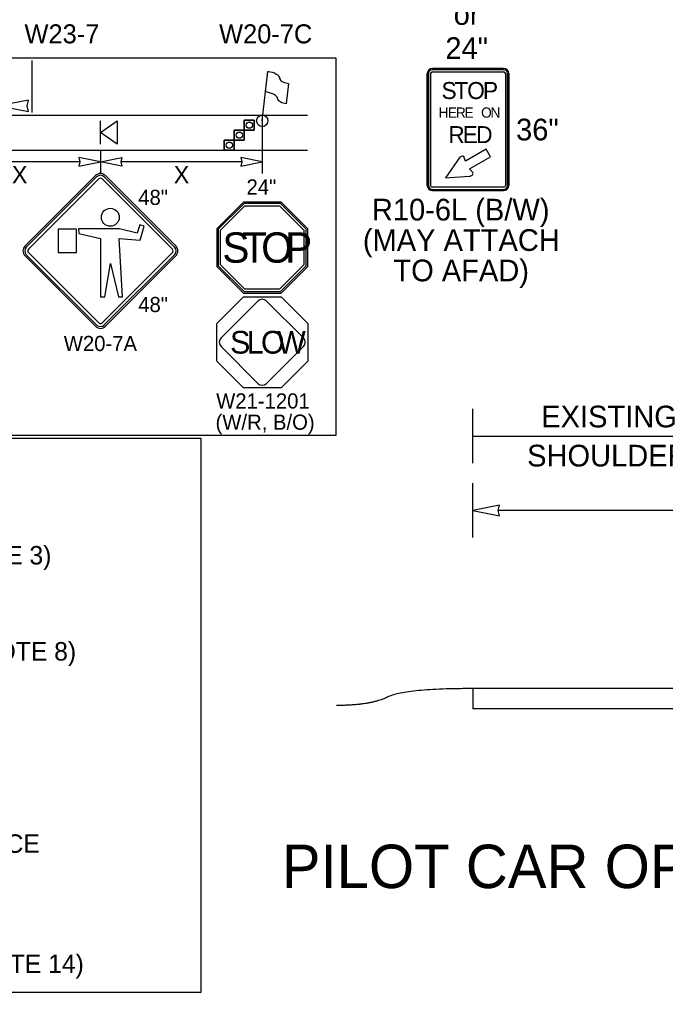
# Model space of a CAD drawing. Extents: x 99999.1 to 100095.7, y 99995 to 100010.7.
# Drawn here: x 100042.622 to 100045, y 100001.176 to 100004.76 of the extents above; entities that cross this region are included whole.
import ezdxf

# ---------------------------------------------------------------- set-up
doc = ezdxf.new("R2010")
doc.units = 0
for name, color, linetype in [('RD_ED_ShoulderPavedEdge', 7, 'Continuous'), ('RD_MK_LineEdgeWhite', 7, 'Continuous'), ('SH_DE_DetailHeading1Text', 7, 'Continuous'), ('TR_SN_ConstructionSigns', 7, 'Continuous'), ('TR_WZ_FlaggingStation', 7, 'Continuous'), ('TR_WZ_PortableSignMountBlk-Org', 7, 'Continuous'), ('TR_WZ_TrafficCone', 7, 'Continuous'), ('TR_WZ_WorkZoneDetails', 7, 'Continuous'), ('TR_WZ_WorkZoneTextCurrent', 7, 'Continuous')]:
    doc.layers.add(name, color=color, linetype=linetype)

msp = doc.modelspace()

# ---------------------------------------------------------------- linework, layer by layer
at = {"layer": 'RD_ED_ShoulderPavedEdge'}
msp.add_line((100040.2, 100004.2788), (100043.6825, 100004.2788), dxfattribs=at)
at = {"layer": 'RD_MK_LineEdgeWhite'}
msp.add_line((100040.2, 100004.4079), (100043.6825, 100004.4079), dxfattribs=at)
at = {"layer": 'TR_SN_ConstructionSigns'}
for p, q in [((100044.4041, 100004.5796), (100044.1416, 100004.5796)), ((100044.1416, 100004.5796), (100044.4041, 100004.5796)), ((100044.4041, 100004.5796), (100044.1416, 100004.5796)), ((100044.4041, 100004.5749), (100044.1416, 100004.5749)), ((100044.1229, 100004.5609), (100044.1229, 100004.1484)), ((100044.1229, 100004.1484), (100044.1229, 100004.5609)), ((100044.1229, 100004.5609), (100044.1229, 100004.1484)), ((100044.1276, 100004.5609), (100044.1276, 100004.1484)), ((100044.1354, 100004.1484), (100044.1354, 100004.5609)), ((100044.1416, 100004.5671), (100044.4041, 100004.5671)), ((100044.4104, 100004.5609), (100044.4104, 100004.1484)), ((100044.4182, 100004.1484), (100044.4182, 100004.5609)), ((100044.4229, 100004.1484), (100044.4229, 100004.5609)), ((100044.4229, 100004.5609), (100044.4229, 100004.1484)), ((100044.4229, 100004.1484), (100044.4229, 100004.5609)), ((100044.2424, 100004.2523), (100044.1898, 100004.1766)), ((100044.3396, 100004.2827), (100044.263, 100004.2385)), ((100044.2786, 100004.2096), (100044.356, 100004.2543)), ((100044.356, 100004.2543), (100044.3396, 100004.2827)), ((100044.263, 100004.2385), (100044.2592, 100004.2511)), ((100042.901, 100004.185), (100042.642, 100003.926)), ((100042.9056, 100004.1804), (100042.6466, 100003.9214)), ((100043.1923, 100003.9214), (100042.9333, 100004.1804)), ((100043.1969, 100003.926), (100042.938, 100004.185)), ((100044.1898, 100004.1766), (100044.2776, 100004.1827)), ((100044.2909, 100004.1959), (100044.2786, 100004.2096)), ((100042.6543, 100003.9137), (100042.9133, 100004.1726)), ((100042.9256, 100004.1726), (100043.1846, 100003.9137)), ((100044.4041, 100004.1421), (100044.1416, 100004.1421)), ((100044.1416, 100004.1343), (100044.4041, 100004.1343)), ((100044.1416, 100004.1296), (100044.4041, 100004.1296)), ((100044.4041, 100004.1296), (100044.1416, 100004.1296)), ((100044.1416, 100004.1296), (100044.4041, 100004.1296)), ((100043.446, 100004.0874), (100043.3479, 100003.9893)), ((100043.4482, 100004.0822), (100043.3531, 100003.9872)), ((100043.3619, 100003.9835), (100043.4518, 100004.0734)), ((100043.5847, 100004.0874), (100043.446, 100004.0874)), ((100043.5825, 100004.0822), (100043.4482, 100004.0822)), ((100043.4518, 100004.0734), (100043.5789, 100004.0734)), ((100043.5789, 100004.0734), (100043.6688, 100003.9835)), ((100043.6775, 100003.9872), (100043.5825, 100004.0822)), ((100043.6828, 100003.9893), (100043.5847, 100004.0874)), ((100043.3479, 100003.9893), (100043.3479, 100003.8506)), ((100043.3531, 100003.9872), (100043.3531, 100003.8528)), ((100043.3619, 100003.8564), (100043.3619, 100003.9835)), ((100043.6688, 100003.9835), (100043.6688, 100003.8564)), ((100043.6775, 100003.8528), (100043.6775, 100003.9872)), ((100043.6828, 100003.8506), (100043.6828, 100003.9893)), ((100042.6466, 100003.8936), (100042.9056, 100003.6347)), ((100042.9133, 100003.6424), (100042.6543, 100003.9013)), ((100043.1846, 100003.9013), (100042.9256, 100003.6424)), ((100042.9333, 100003.6347), (100043.1923, 100003.8936)), ((100042.642, 100003.889), (100042.901, 100003.63)), ((100042.938, 100003.63), (100043.1969, 100003.889)), ((100043.3479, 100003.8506), (100043.446, 100003.7525)), ((100043.3531, 100003.8528), (100043.4482, 100003.7578)), ((100043.4518, 100003.7665), (100043.3619, 100003.8564)), ((100043.6688, 100003.8564), (100043.5789, 100003.7665)), ((100043.5825, 100003.7578), (100043.6775, 100003.8528)), ((100043.5847, 100003.7525), (100043.6828, 100003.8506)), ((100043.446, 100003.7525), (100043.5847, 100003.7525)), ((100043.4482, 100003.7578), (100043.5825, 100003.7578)), ((100043.5789, 100003.7665), (100043.4518, 100003.7665)), ((100043.4996, 100003.7228), (100043.3637, 100003.587)), ((100043.667, 100003.587), (100043.5311, 100003.7228)), ((100043.3637, 100003.5554), (100043.4996, 100003.4195)), ((100043.5311, 100003.4195), (100043.667, 100003.5554))]:
    msp.add_line(p, q, dxfattribs=at)
for points in [[(100042.8394, 100003.9884), (100042.8404, 100003.9716), (100042.9199, 100003.9531), (100042.9199, 100003.7389), (100042.9354, 100003.7389), (100042.9572, 100003.8606), (100042.9863, 100003.7389), (100043.001, 100003.7389), (100042.9881, 100003.953), (100043.0658, 100003.9467), (100043.0805, 100003.9987), (100043.0645, 100004.0032), (100043.0542, 100003.9735), (100042.99, 100003.9884)], [(100042.7635, 100003.9882), (100042.7635, 100003.9012), (100042.8314, 100003.9012), (100042.8314, 100003.9882)], [(100043.6828, 100003.6405), (100043.6828, 100003.5018), (100043.5847, 100003.4037), (100043.446, 100003.4037), (100043.3479, 100003.5018), (100043.3479, 100003.6405), (100043.446, 100003.7386), (100043.5847, 100003.7386)]]:
    msp.add_lwpolyline(points, close=True, dxfattribs=at)
msp.add_circle((100042.9559, 100004.0315), 0.0329, dxfattribs=at)
for centre, radius, start, end in [((100044.1416, 100004.5609), 0.0187, 90, 180), ((100044.1416, 100004.5609), 0.0187, 90, 180), ((100044.1416, 100004.5609), 0.0187, 90, 180), ((100044.1416, 100004.5609), 0.0141, 90, 180), ((100044.4041, 100004.5609), 0.0187, 0, 90), ((100044.4041, 100004.5609), 0.0187, 0, 90), ((100044.4041, 100004.5609), 0.0187, 0, 90), ((100044.4041, 100004.5609), 0.0141, 0, 90), ((100044.1416, 100004.5609), 0.00625, 90, 180), ((100044.4041, 100004.5609), 0.00625, 0, 90), ((100042.9195, 100004.1665), 0.0262, 45, 135), ((100042.9195, 100004.1665), 0.0196, 45, 135), ((100042.9195, 100004.1665), 0.00872, 45, 135), ((100044.1416, 100004.1484), 0.0187, 180, 270), ((100044.1416, 100004.1484), 0.0187, 180, 270), ((100044.1416, 100004.1484), 0.0187, 180, 270), ((100044.1416, 100004.1484), 0.0141, 180, 270), ((100044.1416, 100004.1484), 0.00625, 180, 270), ((100044.4041, 100004.1484), 0.0187, 270, 0), ((100044.4041, 100004.1484), 0.0187, 270, 0), ((100044.4041, 100004.1484), 0.0187, 270, 0), ((100044.4041, 100004.1484), 0.0141, 270, 0), ((100044.4041, 100004.1484), 0.00625, 270, 0), ((100042.6605, 100003.9075), 0.0262, 135, 225), ((100042.6605, 100003.9075), 0.0196, 135, 225), ((100042.6605, 100003.9075), 0.00872, 135, 225), ((100043.1784, 100003.9075), 0.00872, 315, 45), ((100043.1784, 100003.9075), 0.0196, 315, 45), ((100043.1784, 100003.9075), 0.0262, 315, 45), ((100043.5153, 100003.707), 0.0223, 45, 135), ((100042.9195, 100003.6485), 0.00872, 225, 315), ((100042.9195, 100003.6485), 0.0262, 225, 315), ((100042.9195, 100003.6485), 0.0196, 225, 315), ((100043.3795, 100003.5712), 0.0223, 135, 225), ((100043.6512, 100003.5712), 0.0223, 315, 45), ((100043.5153, 100003.4353), 0.0223, 225, 315)]:
    msp.add_arc(centre, radius, start, end, dxfattribs=at)
for centre, major_axis, start_param, end_param in [((100044.2492, 100004.248), (0.00934, 0.00539), 5.977036, 8.198856), ((100044.2816, 100004.1909), (-0.00913, -0.00527), 0.771965, 3.092601)]:
    msp.add_ellipse(centre, major_axis=major_axis, ratio=0.700347, start_param=start_param, end_param=end_param, dxfattribs=at)
at = {"layer": 'TR_WZ_FlaggingStation'}
for p, q in [((100043.5154, 100004.387), (100043.5361, 100004.5684)), ((100043.5277, 100004.4948), (100043.5361, 100004.5686)), ((100043.6123, 100004.5248), (100043.6037, 100004.4491)), ((100043.5277, 100004.4948), (100043.5277, 100004.4948))]:
    msp.add_line(p, q, dxfattribs=at)
for points in [[(100043.5361, 100004.5686), (100043.5398, 100004.5678), (100043.5514, 100004.5656), (100043.5603, 100004.5629), (100043.5665, 100004.559), (100043.5721, 100004.5559), (100043.5757, 100004.5515), (100043.5785, 100004.5464), (100043.5788, 100004.5424), (100043.5823, 100004.5365), (100043.5892, 100004.5317), (100043.5973, 100004.5283), (100043.6123, 100004.5248)], [(100043.6037, 100004.4491), (100043.5985, 100004.45), (100043.587, 100004.453), (100043.5769, 100004.4598), (100043.5727, 100004.4667), (100043.5702, 100004.4733), (100043.5643, 100004.4803), (100043.5572, 100004.4844), (100043.546, 100004.4889), (100043.5277, 100004.4948)]]:
    msp.add_lwpolyline(points, dxfattribs=at)
msp.add_circle((100043.5154, 100004.387), 0.021, dxfattribs=at)
at = {"layer": 'TR_WZ_PortableSignMountBlk-Org'}
msp.add_line((100042.9195, 100004.3003), (100042.9195, 100004.3864), dxfattribs=at)
msp.add_lwpolyline([(100042.9195, 100004.3433), (100042.9813, 100004.3864), (100042.9813, 100004.3003)], close=True, dxfattribs=at)
at = {"layer": 'TR_WZ_TrafficCone'}
for points in [[(100043.4491, 100004.389), (100043.4858, 100004.389), (100043.4858, 100004.3523), (100043.4491, 100004.3523), (100043.4491, 100004.389)], [(100043.4491, 100004.3523), (100043.4858, 100004.3523), (100043.4858, 100004.389), (100043.4491, 100004.389), (100043.4491, 100004.3523)], [(100043.4123, 100004.3523), (100043.4491, 100004.3523), (100043.4491, 100004.3155), (100043.4123, 100004.3155), (100043.4123, 100004.3523)], [(100043.4123, 100004.3155), (100043.4491, 100004.3155), (100043.4491, 100004.3523), (100043.4123, 100004.3523), (100043.4123, 100004.3155)], [(100043.3756, 100004.3155), (100043.4123, 100004.3155), (100043.4123, 100004.2788), (100043.3756, 100004.2788), (100043.3756, 100004.3155)], [(100043.3756, 100004.2788), (100043.4123, 100004.2788), (100043.4123, 100004.3155), (100043.3756, 100004.3155), (100043.3756, 100004.2788)]]:
    msp.add_lwpolyline(points, dxfattribs=at)
for centre in [(100043.4674, 100004.3706), (100043.4307, 100004.3339), (100043.3939, 100004.2971)]:
    msp.add_circle(centre, 0.0115, dxfattribs=at)
at = {"layer": 'TR_WZ_WorkZoneDetails'}
for p, q in [((100042.6686, 100004.4179), (100042.6686, 100004.6086)), ((100043.5154, 100004.4079), (100043.5154, 100004.1926)), ((100042.9195, 100004.2788), (100042.9195, 100004.1926)), ((100042.8438, 100004.2357), (100042.3992, 100004.2357)), ((100043.4397, 100004.2357), (100042.9952, 100004.2357)), ((100044.2907, 100003.1255), (100044.2907, 100003.3255)), ((100044.2907, 100003.2255), (100045.2907, 100003.2255)), ((100044.2907, 100002.8515), (100044.2907, 100003.0515)), ((100046.397, 100002.9515), (100044.3844, 100002.9515)), ((100044.2907, 100002.2954), (100044.2907, 100002.2204)), ((100048.6907, 100002.2954), (100044.2907, 100002.2954)), ((100048.6907, 100002.2204), (100044.2907, 100002.2204))]:
    msp.add_line(p, q, dxfattribs=at)
for points in [[(100042.5458, 100004.4419), (100042.655, 100004.4205), (100042.6499, 100004.4419), (100042.655, 100004.4633)], [(100042.9195, 100004.2357), (100042.8401, 100004.2513), (100042.8438, 100004.2357), (100042.8401, 100004.2201)], [(100042.9195, 100004.2357), (100042.9988, 100004.2513), (100042.9952, 100004.2357), (100042.9988, 100004.2201)], [(100043.5154, 100004.2357), (100043.4361, 100004.2513), (100043.4397, 100004.2357), (100043.4361, 100004.2201)], [(100044.2907, 100002.9515), (100044.389, 100002.9322), (100044.3844, 100002.9515), (100044.389, 100002.9708)]]:
    msp.add_lwpolyline(points, close=True, dxfattribs=at)
msp.add_open_spline([(100044.2907, 100002.2954), (100044.0395, 100002.2954), (100043.914, 100002.2333), (100043.7886, 100002.2333)], degree=2, dxfattribs=at)
at = {"layer": 'TR_WZ_WorkZoneTextCurrent'}
for points in [[(100040.1, 100004.6186), (100043.7858, 100004.6186), (100043.7858, 100003.2274), (100040.1, 100003.2274)], [(100040.1, 100003.2174), (100043.2886, 100003.2174), (100043.2886, 100001.1759), (100040.1, 100001.1759)]]:
    msp.add_lwpolyline(points, close=True, dxfattribs=at)

# ---------------------------------------------------------------- texts
at = {"layer": 'SH_DE_DetailHeading1Text'}
msp.add_text('PILOT CAR OPERATION FOR ALTERNATING 1-LANE, 2-WAY TRAFFIC: AFAD-CONTROLLED + TEMP. RUMBLE STRIPS', height=0.16, rotation=360, dxfattribs=at).set_placement((100043.5871, 100001.5606))
at = {"layer": 'TR_SN_ConstructionSigns'}
for s, height, p in [('or', 0.08, (100044.2201, 100004.7403)), ('W23-7', 0.07, (100042.64, 100004.6721)), ('W20-7C', 0.07, (100043.3563, 100004.6721)), ('24"', 0.08, (100044.1895, 100004.6146)), ('36"', 0.08, (100044.4498, 100004.3146)), ('48"', 0.05581, (100043.0588, 100004.0769)), ('R10-6L (B/W)', 0.08, (100043.919, 100004.0196)), ('(MAY ATTACH', 0.08, (100043.8858, 100003.9076)), ('TO AFAD)', 0.08, (100043.9982, 100003.7956)), ('48"', 0.05581, (100043.0588, 100003.6823)), ('W20-7A', 0.05581, (100042.7847, 100003.5387)), ('W21-1201', 0.05581, (100043.3457, 100003.327)), ('(W/R, B/O)', 0.05581, (100043.3434, 100003.2489))]:
    msp.add_text(s, height=height, rotation=360, dxfattribs=at).set_placement(p)
for s, height, p in [('S', 0.0625, (100044.1754, 100004.4671)), ('T', 0.0625, (100044.2229, 100004.4671)), ('O', 0.0625, (100044.2698, 100004.4671)), ('P', 0.0625, (100044.3279, 100004.4671)), ('H', 0.0375, (100044.1643, 100004.3984)), ('E', 0.0375, (100044.1988, 100004.3984)), ('R', 0.0375, (100044.2284, 100004.3984)), ('E', 0.0375, (100044.2603, 100004.3984)), ('O', 0.0375, (100044.3211, 100004.3984)), ('N', 0.0375, (100044.3559, 100004.3984)), ('R', 0.0625, (100044.2004, 100004.3046)), ('E', 0.0625, (100044.2535, 100004.3046)), ('D', 0.0625, (100044.3029, 100004.3046)), ('24"', 0.05581, (100043.4574, 100004.1153)), ('S', 0.1116, (100043.3686, 100003.8642)), ('T', 0.1116, (100043.4411, 100003.8642)), ('O', 0.1116, (100043.5114, 100003.8642)), ('P', 0.1116, (100043.5996, 100003.8642)), ('S', 0.0837, (100043.3969, 100003.5293)), ('L', 0.0837, (100043.458, 100003.5293)), ('O', 0.0837, (100043.5107, 100003.5293)), ('W', 0.0837, (100043.5702, 100003.5293))]:
    msp.add_text(s, height=height, dxfattribs=at).set_placement(p)
at = {"layer": 'TR_WZ_WorkZoneDetails'}
for s, p in [('EXISTING', (100044.5424, 100003.2575)), ('SHOULDER', (100044.4905, 100003.1135))]:
    msp.add_text(s, height=0.08, rotation=360, dxfattribs=at).set_placement(p)
at = {"layer": 'TR_WZ_WorkZoneTextCurrent'}
for p in [(100042.5935, 100004.156), (100043.1894, 100004.156)]:
    msp.add_text('X', height=0.0646, dxfattribs=at).set_placement(p)
for s, p in [('28" REFLECTIVE TRAFFIC CONE (SEE NOTE 3)', (100040.7009, 100002.7527)), ('28" PORTABLE TUBULAR MARKER (SEE NOTE 8)', (100040.7009, 100002.3987)), ('AUTOMATED FLAGGER ASSISTANCE DEVICE', (100040.7009, 100001.6905)), ('TEMP. PORTABLE RUMBLE STRIP (SEE NOTE 14)', (100040.7009, 100001.2479))]:
    msp.add_text(s, height=0.068, rotation=360, dxfattribs=at).set_placement(p)

doc.saveas('drawing.dxf')
